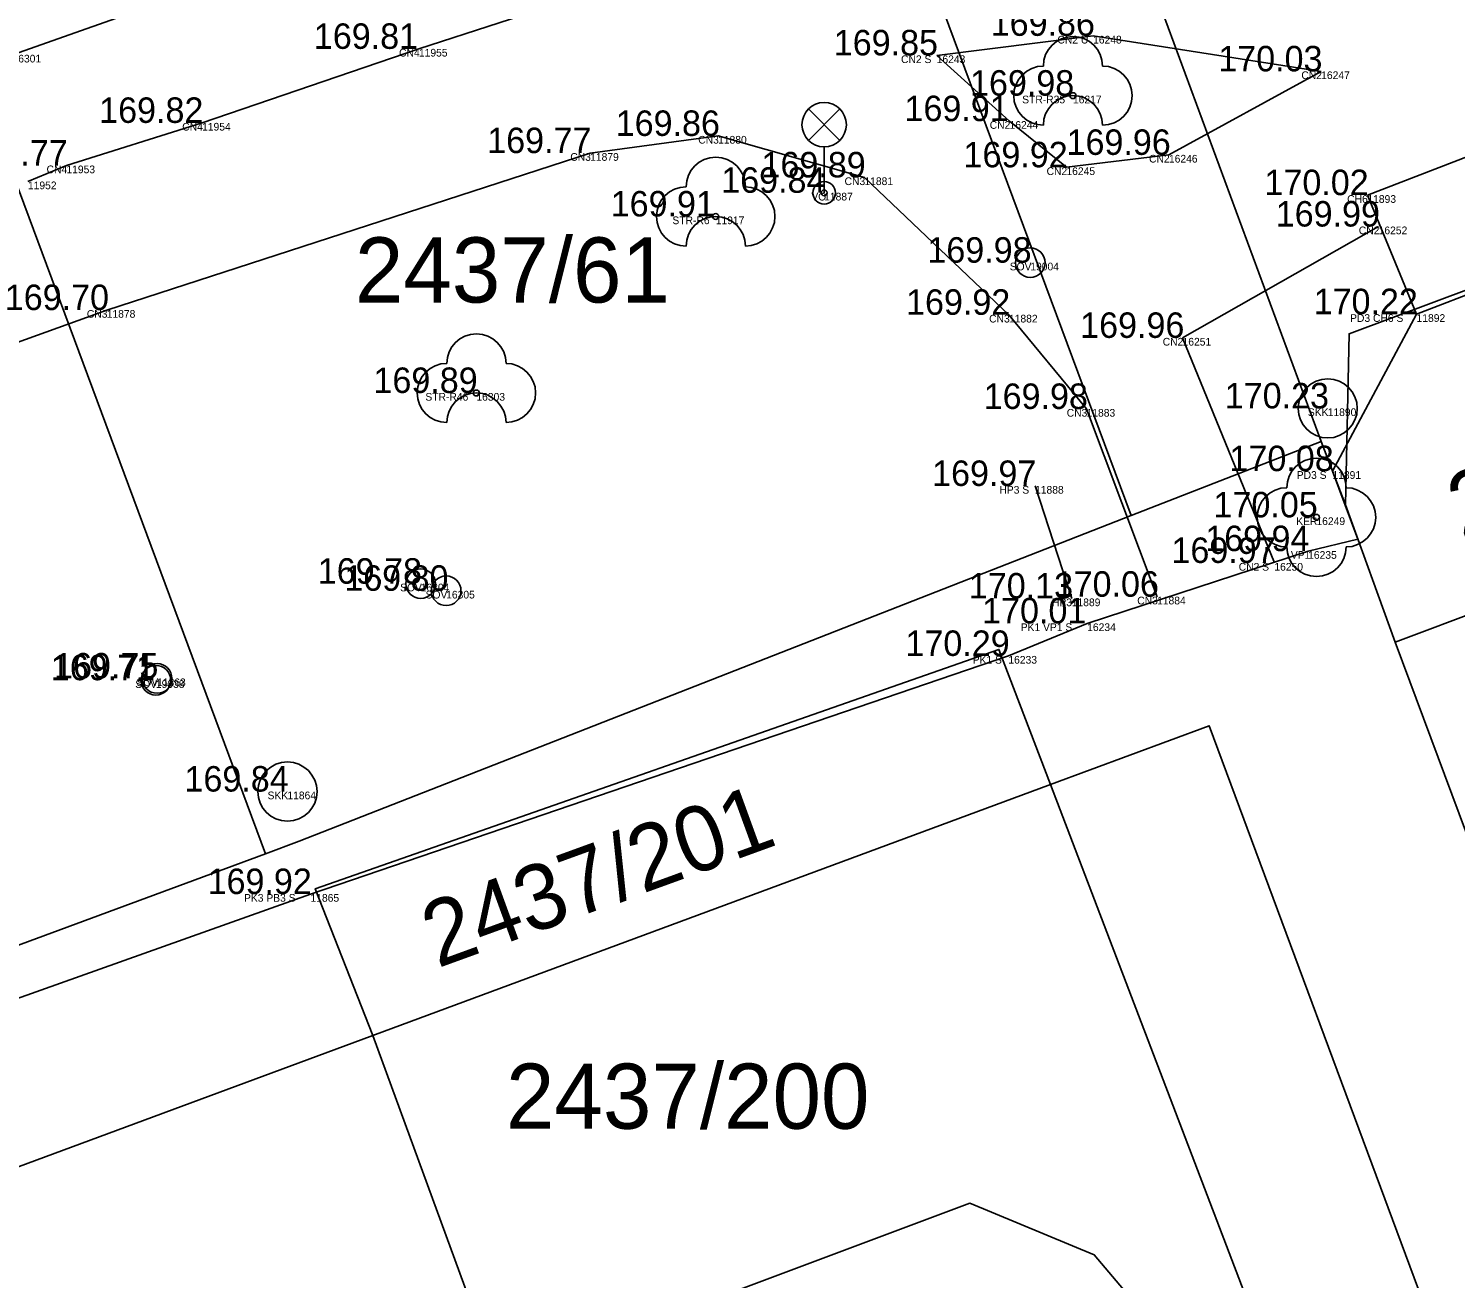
# Model space of a CAD drawing. Extents: x -566117 to -565580, y -1202428 to -1201938.
# Drawn here: x -565905.94 to -565881.85, y -1202258.29 to -1202237.19 of the extents above; entities that cross this region are included whole.
import ezdxf

# ---------------------------------------------------------------- set-up
doc = ezdxf.new("R2010")
doc.units = 0
for name, color, linetype in [('_0', 7, 'Continuous'), ('Bod', 7, 'Continuous'), ('CIZÍ_NADZEM', 7, 'Continuous'), ('Implicitní', 7, 'Continuous'), ('Kanalizace', 7, 'Continuous'), ('Katastr', 7, 'Continuous'), ('Kod', 7, 'Continuous'), ('Oplocení', 7, 'Continuous'), ('Voda', 7, 'Continuous'), ('Vrstva 59', 7, 'Continuous'), ('Výška', 7, 'Continuous'), ('ZELEŇ', 7, 'Continuous'), ('Zpevněné plohy', 7, 'Continuous'), ('Číslo', 7, 'Continuous')]:
    doc.layers.add(name, color=color, linetype=linetype)

# ---------------------------------------------------------------- blocks, each defined once
blk = doc.blocks.new('A$C69D74C1E')
at = {"layer": 'Katastr'}
for p, q in [((171.24, -149.8), (180.81, -175.72)), ((177.6, -176.97), (172.9, -164.32)), ((157.96, -169.15), (162.99, -182.68)), ((180.81, -175.72), (177.6, -176.97)), ((180.81, -175.72), (181.22, -176.79)), ((182.06, -179.11), (181.22, -176.79)), ((184.36, -178.24), (182.06, -179.11)), ((188.46, -196.31), (182.06, -179.11)), ((176.24, -181.51), (164.8, -185.75)), ((176.24, -181.51), (182.8, -198.71)), ((162.99, -182.68), (149.57, -187.65)), ((166.93, -191.56), (164.8, -185.75))]:
    blk.add_line(p, q, dxfattribs=at)
for points in [[(181.22, -176.79), (181.28, -173.9), (189.68, -170.76)], [(177.6, -176.97), (163.56, -182.47), (162.99, -182.68)], [(164.8, -185.75), (163.83, -183.27), (175.37, -179.23), (176.24, -181.51)], [(176.24, -181.51), (178.92, -180.52), (194.57, -222.68)], [(164.8, -185.75), (150.79, -190.94), (166.44, -233.1)], [(180.71, -197.37), (178.18, -190.66), (178, -190.66), (176.98, -189.45), (174.88, -188.58), (166.93, -191.56)]]:
    blk.add_lwpolyline(points, dxfattribs=at)
for s, p in [('2437/61', (164.5, -173.373)), ('2437/200', (167.05, -187.323))]:
    blk.add_text(s, height=1.1, dxfattribs=at).set_placement(p)
for s, rotation, p in [('2437/246', 18, (183.177, -177.381)), ('2437/201', 20, (165.895, -184.615))]:
    blk.add_text(s, height=1.1, rotation=rotation, dxfattribs=at).set_placement(p)
blk = doc.blocks.new('SV')
at = {"layer": 'Voda'}
blk.add_circle((0, 0), 0.25, dxfattribs=at)
blk = doc.blocks.new('STROM')
at = {"layer": 'ZELEŇ'}
blk.add_circle((0, 0), 0.05, dxfattribs=at)
for centre, start, end in [((0, 0.5), 0, 180), ((-0.5, 0), 90, 270), ((0.5, 0), 270, 90), ((0, -0.5), 0, 180)]:
    blk.add_arc(centre, 0.5, start, end, dxfattribs=at)
blk = doc.blocks.new('3.13')
at = {"layer": 'ZELEŇ'}
blk.add_circle((0, 0), 0.1, dxfattribs=at)
for centre, start, end in [((0, 1), 0, 180), ((-1, 0), 90, 270), ((1, 0), 270, 90), ((0, -1), 180, 0)]:
    blk.add_arc(centre, 1, start, end, dxfattribs=at)
blk = doc.blocks.new('SAK')
at = {"layer": 'Kanalizace'}
blk.add_circle((0, 0), 0.5, dxfattribs=at)
blk = doc.blocks.new('LA')
at = {"layer": 'CIZÍ_NADZEM'}
for p, q in [((-0.265, 1.415), (0.265, 0.885)), ((-0.265, 0.885), (0.265, 1.415)), ((0, 0), (0, 0.775))]:
    blk.add_line(p, q, dxfattribs=at)
for centre, radius in [((0, 1.15), 0.375), ((0, 0), 0.19), ((0, 0), 0.05)]:
    blk.add_circle(centre, radius, dxfattribs=at)
blk = doc.blocks.new('POINT_DISPLAY')
at = {"layer": 'Implicitní'}
blk.add_line((0, 0), (0, 0), dxfattribs=at)

msp = doc.modelspace()

# ---------------------------------------------------------------- linework, layer by layer
at = {"layer": '_0'}
msp.add_line((-565906.21, -1202237.63), (-565903.5, -1202236.67), dxfattribs=at)
at = {"layer": 'Oplocení'}
for p, q in [((-565882.51, -1202242.01), (-565879.78, -1202240.95)), ((-565888.07, -1202247.23), (-565884.34, -1202246.01)), ((-565883.501, -1202245.806), (-565884.34, -1202246.01)), ((-565889.4, -1202247.78), (-565888.07, -1202247.23)), ((-565889.4, -1202247.78), (-565901.181, -1202251.8)), ((-565901.18, -1202251.8), (-565913.03, -1202256.02))]:
    msp.add_line(p, q, dxfattribs=at)
msp.add_lwpolyline([(-565883.501, -1202245.806), (-565883.93, -1202244.66), (-565882.51, -1202242.01)], dxfattribs=at)
at = {"layer": 'ZELEŇ'}
msp.add_line((-565888.95, -1202244.91), (-565888.33, -1202246.81), dxfattribs=at)
at = {"layer": 'Zpevněné plohy'}
for p, q in [((-565899.35, -1202237.53), (-565895.78, -1202236.37)), ((-565890.61, -1202237.64), (-565887.97, -1202237.31)), ((-565884.12, -1202237.91), (-565887.97, -1202237.31)), ((-565903.01, -1202238.78), (-565899.35, -1202237.53)), ((-565890.61, -1202237.64), (-565889.38, -1202238.75)), ((-565883.34, -1202240), (-565877.21, -1202237.64)), ((-565886.69, -1202239.32), (-565884.12, -1202237.91)), ((-565905.3, -1202239.5), (-565903.01, -1202238.78)), ((-565889.38, -1202238.75), (-565888.42, -1202239.53)), ((-565896.46, -1202239.29), (-565894.3, -1202239)), ((-565894.3, -1202239), (-565891.83, -1202239.7)), ((-565904.62, -1202241.94), (-565896.46, -1202239.29)), ((-565905.95, -1202239.77), (-565905.3, -1202239.5)), ((-565888.42, -1202239.53), (-565886.69, -1202239.32)), ((-565891.83, -1202239.7), (-565889.39, -1202242.02)), ((-565882.51, -1202242.01), (-565883.34, -1202240)), ((-565886.46, -1202242.41), (-565883.15, -1202240.53)), ((-565911.54, -1202244.44), (-565904.62, -1202241.94)), ((-565889.39, -1202242.02), (-565888.08, -1202243.61)), ((-565884.91, -1202246.21), (-565886.46, -1202242.41)), ((-565888.08, -1202243.61), (-565886.89, -1202246.78))]:
    msp.add_line(p, q, dxfattribs=at)

# ---------------------------------------------------------------- block references
at = {"layer": 'Bod'}
for p in [(-565887.97, -1202237.31), (-565899.35, -1202237.53), (-565890.61, -1202237.64), (-565884.12, -1202237.91), (-565888.31, -1202238.32), (-565903.01, -1202238.78), (-565889.38, -1202238.75), (-565894.3, -1202239), (-565896.46, -1202239.29), (-565905.3, -1202239.5), (-565888.42, -1202239.53), (-565886.69, -1202239.32), (-565891.83, -1202239.7), (-565892.51, -1202239.96), (-565883.34, -1202240), (-565894.34, -1202240.36), (-565883.15, -1202240.53), (-565889.03, -1202241.14), (-565904.62, -1202241.94), (-565889.39, -1202242.02), (-565882.51, -1202242.01), (-565886.46, -1202242.41), (-565898.38, -1202243.34), (-565888.08, -1202243.61), (-565884.01, -1202243.6), (-565883.93, -1202244.66), (-565888.95, -1202244.91), (-565884.2, -1202245.44), (-565884.34, -1202246.01), (-565884.91, -1202246.21), (-565899.32, -1202246.56), (-565898.89, -1202246.68), (-565888.33, -1202246.81), (-565886.89, -1202246.78), (-565888.07, -1202247.23), (-565889.4, -1202247.78), (-565903.79, -1202248.19), (-565903.77, -1202248.16), (-565901.57, -1202250.07), (-565901.18, -1202251.8)]:
    msp.add_blockref('POINT_DISPLAY', p, dxfattribs=at)
at = {"layer": 'CIZÍ_NADZEM'}
msp.add_blockref('LA', (-565892.51, -1202239.96), dxfattribs=at)
at = {"layer": 'Implicitní'}
msp.add_blockref('A$C69D74C1E', (-566064.93, -1202068.44), dxfattribs=at)
at = {"layer": 'Kanalizace'}
for p in [(-565884.01, -1202243.6), (-565901.57, -1202250.07)]:
    msp.add_blockref('SAK', p, dxfattribs=at)
at = {"layer": 'Voda'}
for p in [(-565889.03, -1202241.14), (-565899.32, -1202246.56), (-565898.89, -1202246.68), (-565903.79, -1202248.19), (-565903.77, -1202248.16)]:
    msp.add_blockref('SV', p, dxfattribs=at)
at = {"layer": 'Vrstva 59', "xscale": 0.5, "yscale": 0.5}
msp.add_blockref('3.13', (-565884.2, -1202245.44), dxfattribs=at)
at = {"layer": 'ZELEŇ'}
for p in [(-565888.31, -1202238.32), (-565894.34, -1202240.36), (-565898.38, -1202243.34)]:
    msp.add_blockref('STROM', p, dxfattribs=at)

# ---------------------------------------------------------------- texts
at = {"layer": 'Kod'}
for s, p in [('CN2 U', (-565888.572, -1202237.44)), ('CN4', (-565899.685, -1202237.66)), ('CN2 S', (-565891.212, -1202237.77)), ('CN2', (-565884.455, -1202238.04)), ('STR-R35', (-565889.167, -1202238.45)), ('CN4', (-565903.345, -1202238.91)), ('CN2', (-565889.715, -1202238.88)), ('CN3', (-565894.635, -1202239.13)), ('CN3', (-565896.795, -1202239.42)), ('CN4', (-565905.635, -1202239.63)), ('CN2', (-565888.755, -1202239.66)), ('CN2', (-565887.025, -1202239.45)), ('CN3', (-565892.165, -1202239.83)), ('VO', (-565892.726, -1202240.09)), ('CH6', (-565883.681, -1202240.13)), ('STR-R6', (-565895.071, -1202240.49)), ('CN2', (-565883.485, -1202240.66)), ('SOV', (-565889.377, -1202241.27)), ('CN3', (-565904.955, -1202242.07)), ('CN3', (-565889.725, -1202242.15)), ('PD3 CH6 S', (-565883.632, -1202242.14)), ('CN2', (-565886.795, -1202242.54)), ('STR-R46', (-565899.241, -1202243.47)), ('CN3', (-565888.415, -1202243.74)), ('SKK', (-565884.345, -1202243.73)), ('PD3 S', (-565884.532, -1202244.79)), ('HP3 S', (-565889.552, -1202245.04)), ('KER', (-565884.541, -1202245.57)), ('VP1', (-565884.632, -1202246.14)), ('CN2 S', (-565885.512, -1202246.34)), ('SOV', (-565899.667, -1202246.69)), ('SOV', (-565899.237, -1202246.81)), ('HP3', (-565888.665, -1202246.94)), ('CN3', (-565887.225, -1202246.91)), ('PK1 VP1 S', (-565889.192, -1202247.36)), ('PK1 S', (-565890.002, -1202247.91)), ('SOV', (-565904.137, -1202248.32)), ('SOV', (-565904.117, -1202248.29)), ('SKK', (-565901.905, -1202250.2)), ('PK3 PB3 S', (-565902.302, -1202251.93))]:
    msp.add_text(s, height=0.13, dxfattribs=at).set_placement(p)
at = {"layer": 'Výška'}
for s, p in [('169.86 ', (-565889.698, -1202237.31)), ('169.81 ', (-565901.123, -1202237.53)), ('169.85 ', (-565892.347, -1202237.64)), ('170.03 ', (-565885.857, -1202237.91)), ('169.98 ', (-565890.047, -1202238.32)), ('169.91 ', (-565891.153, -1202238.75)), ('169.82 ', (-565904.747, -1202238.78)), ('169.86 ', (-565896.028, -1202239)), ('169.77 ', (-565898.197, -1202239.29)), ('169.96 ', (-565888.418, -1202239.32)), ('169.77 ', (-565907.037, -1202239.5)), ('169.89 ', (-565893.567, -1202239.7)), ('169.92 ', (-565890.157, -1202239.53)), ('169.84 ', (-565894.247, -1202239.96)), ('170.02 ', (-565885.077, -1202240)), ('169.91 ', (-565896.113, -1202240.36)), ('169.99 ', (-565884.887, -1202240.53)), ('169.98 ', (-565890.767, -1202241.14)), ('169.70 ', (-565906.34, -1202241.94)), ('169.92 ', (-565891.127, -1202242.02)), ('170.22 ', (-565884.247, -1202242.01)), ('169.96 ', (-565888.188, -1202242.41)), ('169.89 ', (-565900.117, -1202243.34)), ('169.98 ', (-565889.817, -1202243.61)), ('170.23 ', (-565885.747, -1202243.6)), ('170.08 ', (-565885.667, -1202244.66)), ('169.97 ', (-565890.687, -1202244.91)), ('170.05 ', (-565885.937, -1202245.44)), ('169.97 ', (-565886.647, -1202246.21)), ('169.94 ', (-565886.077, -1202246.01)), ('169.78 ', (-565901.057, -1202246.56)), ('169.80 ', (-565900.61, -1202246.68)), ('170.13 ', (-565890.067, -1202246.81)), ('170.06 ', (-565888.618, -1202246.78)), ('170.01 ', (-565889.843, -1202247.23)), ('170.29 ', (-565891.137, -1202247.78)), ('169.75 ', (-565905.507, -1202248.16)), ('169.71 ', (-565905.563, -1202248.19)), ('169.84 ', (-565903.307, -1202250.07)), ('169.92 ', (-565902.917, -1202251.8))]:
    msp.add_text(s, height=0.43, dxfattribs=at).set_placement(p)
at = {"layer": 'Číslo'}
for s, p in [('16248', (-565887.97, -1202237.44)), ('11955', (-565899.35, -1202237.66)), ('16301', (-565906.21, -1202237.76)), ('16243', (-565890.61, -1202237.77)), ('16247', (-565884.12, -1202238.04)), ('16217', (-565888.31, -1202238.45)), ('11954', (-565903.01, -1202238.91)), ('16244', (-565889.38, -1202238.88)), ('11880', (-565894.3, -1202239.13)), ('11879', (-565896.46, -1202239.42)), ('11953', (-565905.3, -1202239.63)), ('16245', (-565888.42, -1202239.66)), ('16246', (-565886.69, -1202239.45)), ('11952', (-565905.95, -1202239.9)), ('11881', (-565891.83, -1202239.83)), ('11887', (-565892.51, -1202240.09)), ('11893', (-565883.34, -1202240.13)), ('11917', (-565894.34, -1202240.49)), ('16252', (-565883.15, -1202240.66)), ('19004', (-565889.03, -1202241.27)), ('11878', (-565904.62, -1202242.07)), ('11882', (-565889.39, -1202242.15)), ('11892', (-565882.51, -1202242.14)), ('16251', (-565886.46, -1202242.54)), ('16303', (-565898.38, -1202243.47)), ('11883', (-565888.08, -1202243.74)), ('11890', (-565884.01, -1202243.73)), ('11891', (-565883.93, -1202244.79)), ('11888', (-565888.95, -1202245.04)), ('16249', (-565884.2, -1202245.57)), ('16235', (-565884.34, -1202246.14)), ('16250', (-565884.91, -1202246.34)), ('16304', (-565899.32, -1202246.69)), ('16305', (-565898.89, -1202246.81)), ('11889', (-565888.33, -1202246.94)), ('11884', (-565886.89, -1202246.91)), ('16234', (-565888.07, -1202247.36)), ('16233', (-565889.4, -1202247.91)), ('19038', (-565903.79, -1202248.32)), ('11863', (-565903.77, -1202248.29)), ('11864', (-565901.57, -1202250.2)), ('11865', (-565901.18, -1202251.93))]:
    msp.add_text(s, height=0.13, dxfattribs=at).set_placement(p)

doc.saveas('drawing.dxf')
